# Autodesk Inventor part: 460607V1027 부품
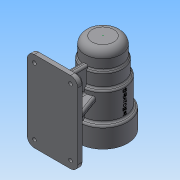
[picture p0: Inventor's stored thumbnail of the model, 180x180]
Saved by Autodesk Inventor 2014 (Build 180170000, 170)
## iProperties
Created: 2016-06
Part Number: 460607V1027 부품
Material: 일반
Document SubType Name: Modeling
Designer: NET
Density: 1 g/cm^3
Appearance: 기본값
Author: NET
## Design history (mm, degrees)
sketch "스케치6"
  geometry: L1 (0, 0)-(25, 0); L2 (25, 0)-(25, -25); L3 (25, -25)-(27, -25); L4 (27, -25)-(27, -45); L5 (27, -45)-(30, -45); L6 (30, -45)-(30, -84); L7 (30, -84)-(34, -84); L8 (34, -84)-(34, -112); L9 (34, -112)-(0, -112); L10 (0, -112)-(0, 0)
  constraints: 20 end point, 8 parallel, 1 horizontal, 1 perpendicular
  dimensions: "d13" = 112 distance between parallel lines of L1 L9; "d14" = 84 distance between parallel lines of L7 L1; "d15" = 45 distance between parallel lines of L1 L5; "d16" = 25 distance between parallel lines of L3 L1; "d17" = 25 distance between parallel lines of L10 L2; "d18" = 27 distance between parallel lines of L10 L4; "d19" = 30 distance between parallel lines of L10 L6; "d20" = 34 distance between parallel lines of L10 L8
revolve "회전1" sketch "스케치6" stored, may be unused: angle "d21" = 90 deg
sketch "스케치7"
  geometry: 1 further point
node "작업 평면1"
sketch "스케치8"
  geometry: L1 (-35, 0)-(35, 0); L2 (35, 0)-(35, -112); L3 (35, -112)-(-35, -112); L4 (-35, -112)-(-35, 0); 2 further points
  constraints: 8 end point, 2 parallel, 1 coincident, 1 horizontal, 1 midpoint, 1 perpendicular
  dimensions: "d23" = 70 distance of L1.start L1.end; "d24" = 112 distance from line of L2.end L1
extrude "돌출5" join sketch "스케치8" distance "d25" = 10; taper "d26" = 0 deg
sketch "스케치9"
  geometry: L1 (-70, 0)-(-60, 0) reference; L2 (-70, -112)-(-60, -112) reference; L3 (-34, -84)-(-34, -112) reference; L4 (-30, -45)-(-30, -84) reference; L5 (-27, -25)-(-27, -45) reference; L6 (-25, 0)-(-25, -25) reference; L7 (-70, -92)-(-12.802, -92); L8 (-70, -20)-(-12.802, -20); L9 (-12.802, -20)-(-12.802, -92); L10 (-70, -20)-(-70, -92); 1 further point
  constraints: 8 end point, 3 parallel, 2 perpendicular
  dimensions: "d29" = 20 distance between parallel lines of L2 L7; "d30" = 20 distance between parallel lines of L1 L8; "d31" = 57.19766 distance between parallel lines of L9 L10; "d32" = 17.19766 distance between parallel lines of L4 L9
extrude "돌출6" join sketch "스케치9" stored distance "d33" = 8; taper "d34" = 0 deg
node "작업 평면2"
sketch "스케치10"
  geometry: 1 further point
fillet "모깎기1" dims "d35" = 10
chamfer "모따기1" distance "d36" = 4; stored, may be unused: second distance "d37" = 2, angle "d38" = 45 deg
sketch "스케치11"
  geometry: L1 (10, 10)-(60, 10) reference; L2 (60, 10)-(66, 10) reference; L3 (4, 10)-(10, 10) reference; L4 (63, 10)-(48.168, 50.749); L5 (7, 10)-(21.832, 50.749); L6 (21.832, 50.749)-(48.168, 50.749); L7 (7, 10)-(63, 10); L8 (35, 50.749)-(35, 10); 1 further point
  constraints: 10 end point, 3 midpoint, 1 collinear
  dimensions: "d42" = 26.3369 distance of L5.end L4.end; "d43" = 43.36455 distance of L5.start L5.end; "d44" = 70 deg angle of L1 L5; "d45" = 20 deg angle of L4 L8; "d46" = 20 deg angle of L5 L8
extrude "돌출7" join sketch "스케치11" stored distance "d47" = 8; taper "d48" = 0 deg
fillet "모깎기2" dims "d49" = 3
fillet "모깎기3" dims "d50" = 3
fillet "모깎기4" dims "d51" = 3
fillet "모깎기5" dims "d52" = 3
fillet "모깎기6" dims "d53" = 10
sketch "스케치12"
  geometry: C1 r 34 at (0, 0) reference; C2 r 21 at (0, 0)
  constraints: 1 centre point, 1 coincident
  dimensions: "d54" = 42 diameter of C2
extrude "돌출8" cut sketch "스케치12" distance "d55" = 15; taper "d56" = 0 deg
sketch "스케치13"
  geometry: C1 r 21 at (0, 0) reference; C2 r 24 at (0, 0)
  constraints: 1 centre point, 1 coincident
  dimensions: "d57" = 48 diameter of C2
extrude "돌출9" cut sketch "스케치13" distance "d58" = 54; taper "d59" = 0 deg
sketch "스케치14"
  geometry: C1 r 24 at (0, 0) reference; C2 r 21 at (0, 0)
  constraints: 1 centre point, 1 coincident
  dimensions: "d60" = 42 diameter of C2
extrude "돌출10" cut sketch "스케치14" distance "d61" = 12; taper "d62" = 0 deg
sketch "스케치15"
  geometry: C1 r 21 at (0, 0) reference; C2 r 17.5 at (0, 0)
  constraints: 1 centre point, 1 coincident
  dimensions: "d63" = 35 diameter of C2
extrude "돌출11" cut sketch "스케치15" distance "d64" = 18; taper "d65" = 0 deg
sketch "스케치16"
  geometry: C1 r 17.5 at (0, 0) reference; C2 r 16 at (0, 0)
  constraints: 1 centre point, 1 coincident
  dimensions: "d66" = 32 diameter of C2
extrude "돌출12" cut sketch "스케치16" distance "d67" = 4; taper "d68" = 0 deg
sketch "스케치17"
  geometry: C1 r 16 at (0, 0) reference; C2 r 10.5 at (0, 0)
  constraints: 1 centre point, 1 coincident
  dimensions: "d69" = 21 diameter of C2
extrude "돌출13" cut sketch "스케치17" distance "d70" = 3; taper "d71" = 0 deg
fillet "모깎기7" dims "d72" = 3
fillet "모깎기8" dims "d73" = 0.3
fillet "모깎기9" dims "d74" = 3
fillet "모깎기10" dims "d75" = 3
chamfer "모따기2" distance "d76" = 1; stored, may be unused: second distance "d77" = 2, angle "d78" = 45 deg
sketch "스케치19" dims "d79" = 52
  geometry: L1 (0, 0)-(0, 26); C1 r 22 at (0, 0) reference; 1 further point
  constraints: 2 coincident, 2 end point, 1 vertical, 1 vertical alignment, 2 other
hole "구멍1" sketch "스케치19" at (0, 26) diameter "d80" = 4; stored, may be unused: countersink angle "d84" = 90 deg, drill point angle "d86" = 118 deg; dims "d81" = 6, "d82" = 4, "d83" = 2, "d85" = 11
feature "스레드1" dims "d87" = 8, "d88" = 0
node "작업 평면3"
sketch "스케치20"
  geometry: L1 (-34, -112)-(34, -112) reference; 2 further points
  constraints: 1 other
  dimensions: "d93" = 48 distance from line of L1 point (0, -64); "d94" = 0 horizontal distance of point (0, -64) point (0, 0)
feature "엠보싱1" sketch "스케치20" dims "d25" = 10, "d95" = 0.5, "d96" = 0
sketch "스케치22"
  geometry: C1 r 4.5 at (-25, 102); C2 r 4.5 at (-25, 10); C3 r 2.5 at (-25, 10); C4 r 2.5 at (-25, 102); A1 r 6 centre (-25, 102) between (-25, 108) and (-31, 102) reference; A2 r 6 centre (-25, 10) between (-31, 10) and (-25, 4) reference; 1 further point
  constraints: 4 centre point, 4 coincident
  dimensions: "d99" = 9 diameter of C1; "d100" = 9 diameter of C2; "d102" = 5 diameter of C3; "d103" = 5 diameter of C4
extrude "돌출14" cut sketch "스케치22" distance "d104" = 4; taper "d105" = 0 deg
extrude "돌출15" cut sketch "스케치22" stored distance "d106" = 4; taper "d107" = 0 deg
node "작업 평면4"
node "솔리드2"
pattern_circular "원형 패턴1" dims angle "d90" = 360 deg
mirror "대칭1"
